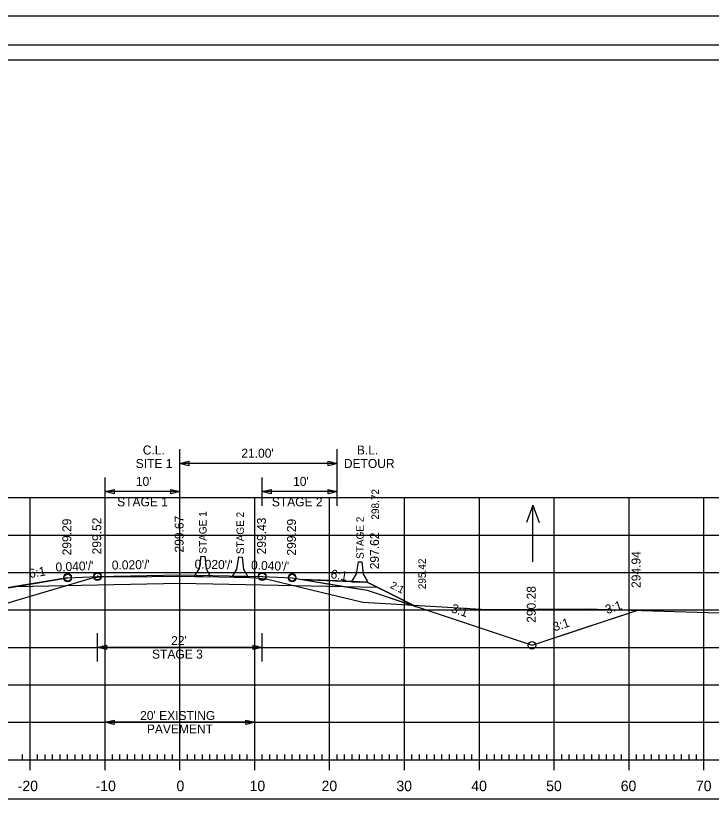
# Model space of a CAD drawing. Extents: x 1368713 to 1370673, y 380279 to 380950.
# Drawn here: x 1370130.4 to 1370223.2, y 380418.3 to 380523.8 of the extents above; entities that cross this region are included whole.
import ezdxf

# ---------------------------------------------------------------- set-up
doc = ezdxf.new("R2010")
doc.units = 0
for name, color, linetype in [('R_Alt Surface', 7, 'Continuous'), ('R_Axis', 7, 'Continuous'), ('R_Axis Annot', 7, 'Continuous'), ('R_Border', 7, 'Continuous'), ('R_CONC BARRIER', 7, 'Continuous'), ('R_Exist Surface', 7, 'Continuous'), ('R_Fin Surface', 7, 'Continuous'), ('R_Grid', 7, 'Continuous'), ('R_No Plot', 7, 'Continuous'), ('R_ROW Annot', 7, 'Continuous'), ('R_Stage 3 EW', 7, 'Continuous'), ('R_Water Annot', 7, 'Continuous'), ('R_Xsect Elev', 7, 'Continuous'), ('R_Xsect Slope', 7, 'Continuous')]:
    doc.layers.add(name, color=color, linetype=linetype)

msp = doc.modelspace()

# ---------------------------------------------------------------- linework, layer by layer
for points in [[(1370141.28, 380449.01), (1370141.28, 380448.94), (1370141.28, 380448.87), (1370141.28, 380448.85), (1370141.28, 380448.84)], [(1370163.28, 380448.94), (1370163.28, 380448.87), (1370163.28, 380448.85), (1370163.28, 380448.84)]]:
    msp.add_lwpolyline(points)
at = {"layer": 'R_Alt Surface'}
for points in [[(1370137.28, 380448.71), (1370127.28, 380447.04)], [(1370130.44, 380447.57), (1370141.28, 380447.78), (1370152.28, 380448), (1370163.28, 380447.78), (1370174.12, 380447.57)], [(1370167.28, 380448.71), (1370177.28, 380447.04)], [(1370177.28, 380448.14), (1370183.88, 380444.84)], [(1370174.12, 380447.57), (1370178.61, 380447.48)], [(1370177.28, 380447.04), (1370199.31, 380439.7)], [(1370199.31, 380439.7), (1370199.31, 380439.7), (1370213.3, 380444.36)]]:
    msp.add_lwpolyline(points, dxfattribs=at)
at = {"layer": 'R_Axis'}
for p, q in [((1370132.28, 380423.02), (1370132.28, 380425.82)), ((1370142.28, 380423.02), (1370142.28, 380425.82)), ((1370152.28, 380423.02), (1370152.28, 380425.82)), ((1370162.28, 380423.02), (1370162.28, 380425.82)), ((1370172.28, 380423.02), (1370172.28, 380425.82)), ((1370182.28, 380423.02), (1370182.28, 380425.82)), ((1370192.28, 380423.02), (1370192.28, 380425.82)), ((1370202.28, 380423.02), (1370202.28, 380425.82)), ((1370212.28, 380423.02), (1370212.28, 380425.82)), ((1370222.28, 380423.02), (1370222.28, 380425.82)), ((1370131.28, 380424.42), (1370131.28, 380425.12)), ((1370133.28, 380424.42), (1370133.28, 380425.12)), ((1370134.28, 380424.42), (1370134.28, 380425.12)), ((1370135.28, 380424.42), (1370135.28, 380425.12)), ((1370136.28, 380424.42), (1370136.28, 380425.12)), ((1370137.28, 380424.42), (1370137.28, 380425.12)), ((1370138.28, 380424.42), (1370138.28, 380425.12)), ((1370139.28, 380424.42), (1370139.28, 380425.12)), ((1370140.28, 380424.42), (1370140.28, 380425.12)), ((1370141.28, 380424.42), (1370141.28, 380425.12)), ((1370143.28, 380424.42), (1370143.28, 380425.12)), ((1370144.28, 380424.42), (1370144.28, 380425.12)), ((1370145.28, 380424.42), (1370145.28, 380425.12)), ((1370146.28, 380424.42), (1370146.28, 380425.12)), ((1370147.28, 380424.42), (1370147.28, 380425.12)), ((1370148.28, 380424.42), (1370148.28, 380425.12)), ((1370149.28, 380424.42), (1370149.28, 380425.12)), ((1370150.28, 380424.42), (1370150.28, 380425.12)), ((1370151.28, 380424.42), (1370151.28, 380425.12)), ((1370153.28, 380424.42), (1370153.28, 380425.12)), ((1370154.28, 380424.42), (1370154.28, 380425.12)), ((1370155.28, 380424.42), (1370155.28, 380425.12)), ((1370156.28, 380424.42), (1370156.28, 380425.12)), ((1370157.28, 380424.42), (1370157.28, 380425.12)), ((1370158.28, 380424.42), (1370158.28, 380425.12)), ((1370159.28, 380424.42), (1370159.28, 380425.12)), ((1370160.28, 380424.42), (1370160.28, 380425.12)), ((1370161.28, 380424.42), (1370161.28, 380425.12)), ((1370163.28, 380424.42), (1370163.28, 380425.12)), ((1370164.28, 380424.42), (1370164.28, 380425.12)), ((1370165.28, 380424.42), (1370165.28, 380425.12)), ((1370166.28, 380424.42), (1370166.28, 380425.12)), ((1370167.28, 380424.42), (1370167.28, 380425.12)), ((1370168.28, 380424.42), (1370168.28, 380425.12)), ((1370169.28, 380424.42), (1370169.28, 380425.12)), ((1370170.28, 380424.42), (1370170.28, 380425.12)), ((1370171.28, 380424.42), (1370171.28, 380425.12)), ((1370173.28, 380424.42), (1370173.28, 380425.12)), ((1370174.28, 380424.42), (1370174.28, 380425.12)), ((1370175.28, 380424.42), (1370175.28, 380425.12)), ((1370176.28, 380424.42), (1370176.28, 380425.12)), ((1370177.28, 380424.42), (1370177.28, 380425.12)), ((1370178.28, 380424.42), (1370178.28, 380425.12)), ((1370179.28, 380424.42), (1370179.28, 380425.12)), ((1370180.28, 380424.42), (1370180.28, 380425.12)), ((1370181.28, 380424.42), (1370181.28, 380425.12)), ((1370183.28, 380424.42), (1370183.28, 380425.12)), ((1370184.28, 380424.42), (1370184.28, 380425.12)), ((1370185.28, 380424.42), (1370185.28, 380425.12)), ((1370186.28, 380424.42), (1370186.28, 380425.12)), ((1370187.28, 380424.42), (1370187.28, 380425.12)), ((1370188.28, 380424.42), (1370188.28, 380425.12)), ((1370189.28, 380424.42), (1370189.28, 380425.12)), ((1370190.28, 380424.42), (1370190.28, 380425.12)), ((1370191.28, 380424.42), (1370191.28, 380425.12)), ((1370193.28, 380424.42), (1370193.28, 380425.12)), ((1370194.28, 380424.42), (1370194.28, 380425.12)), ((1370195.28, 380424.42), (1370195.28, 380425.12)), ((1370196.28, 380424.42), (1370196.28, 380425.12)), ((1370197.28, 380424.42), (1370197.28, 380425.12)), ((1370198.28, 380424.42), (1370198.28, 380425.12)), ((1370199.28, 380424.42), (1370199.28, 380425.12)), ((1370200.28, 380424.42), (1370200.28, 380425.12)), ((1370201.28, 380424.42), (1370201.28, 380425.12)), ((1370203.28, 380424.42), (1370203.28, 380425.12)), ((1370204.28, 380424.42), (1370204.28, 380425.12)), ((1370205.28, 380424.42), (1370205.28, 380425.12)), ((1370206.28, 380424.42), (1370206.28, 380425.12)), ((1370207.28, 380424.42), (1370207.28, 380425.12)), ((1370208.28, 380424.42), (1370208.28, 380425.12)), ((1370209.28, 380424.42), (1370209.28, 380425.12)), ((1370210.28, 380424.42), (1370210.28, 380425.12)), ((1370211.28, 380424.42), (1370211.28, 380425.12)), ((1370213.28, 380424.42), (1370213.28, 380425.12)), ((1370214.28, 380424.42), (1370214.28, 380425.12)), ((1370215.28, 380424.42), (1370215.28, 380425.12)), ((1370216.28, 380424.42), (1370216.28, 380425.12)), ((1370217.28, 380424.42), (1370217.28, 380425.12)), ((1370218.28, 380424.42), (1370218.28, 380425.12)), ((1370219.28, 380424.42), (1370219.28, 380425.12)), ((1370220.28, 380424.42), (1370220.28, 380425.12)), ((1370221.28, 380424.42), (1370221.28, 380425.12)), ((1370012.28, 380424.42), (1370292.28, 380424.42))]:
    msp.add_line(p, q, dxfattribs=at)
at = {"layer": 'R_Border'}
for p, q in [((1369994.28, 380519.88), (1370310.46, 380519.88)), ((1370146.8, 380519.62), (1370146.8, 380519.62)), ((1370146.8, 380519.62), (1370146.8, 380519.62))]:
    msp.add_line(p, q, dxfattribs=at)
at = {"layer": 'R_CONC BARRIER'}
for p, q in [((1370155.09, 380451.58), (1370155.59, 380451.57)), ((1370160.09, 380451.5), (1370160.59, 380451.49)), ((1370176.09, 380450.86), (1370176.59, 380450.85)), ((1370154.28, 380448.89), (1370154.29, 380449.06)), ((1370154.28, 380448.89), (1370156.28, 380448.85)), ((1370156.28, 380448.85), (1370156.29, 380449.02)), ((1370159.28, 380448.82), (1370159.29, 380448.99)), ((1370159.28, 380448.82), (1370161.28, 380448.78)), ((1370161.28, 380448.78), (1370161.29, 380448.95)), ((1370175.28, 380448.18), (1370175.29, 380448.35)), ((1370175.28, 380448.18), (1370177.28, 380448.14)), ((1370177.28, 380448.14), (1370177.29, 380448.31))]:
    msp.add_line(p, q, dxfattribs=at)
for points in [[(1370155.09, 380451.58), (1370154.84, 380449.94), (1370154.29, 380449.06)], [(1370155.59, 380451.57), (1370155.77, 380449.92), (1370156.29, 380449.02)], [(1370160.09, 380451.5), (1370159.84, 380449.87), (1370159.29, 380448.99)], [(1370160.59, 380451.49), (1370160.77, 380449.85), (1370161.29, 380448.95)], [(1370176.09, 380450.86), (1370175.84, 380449.23), (1370175.29, 380448.35)], [(1370176.59, 380450.85), (1370176.77, 380449.21), (1370177.29, 380448.31)]]:
    msp.add_lwpolyline(points, dxfattribs=at)
at = {"layer": 'R_Exist Surface'}
msp.add_lwpolyline([(1370127.85, 380444.92), (1370130.37, 380445.68), (1370140.63, 380448.69), (1370141.3, 380448.78), (1370141.85, 380448.86), (1370148.53, 380448.9), (1370151.93, 380448.92), (1370155.37, 380448.88), (1370161.6, 380448.77), (1370162.51, 380448.71), (1370163.96, 380448.53), (1370169.84, 380447.12), (1370176.72, 380445.46), (1370193.29, 380444.5), (1370206.6, 380444.55), (1370231.71, 380443.82), (1370238.87, 380443.76), (1370241.47, 380442.81), (1370252.47, 380438.45), (1370256.7, 380438.5), (1370261.72, 380438.46), (1370272.45, 380441.8), (1370280.64, 380444.29), (1370292.28, 380444.39)], dxfattribs=at)
at = {"layer": 'R_Fin Surface'}
for points in [[(1370086.4, 380444.54), (1370095.2, 380441.62), (1370103.09, 380438.98), (1370127.28, 380447.04), (1370130.44, 380447.57), (1370137.28, 380448.71), (1370141.28, 380448.87), (1370152.28, 380449.09), (1370163.28, 380448.87), (1370167.28, 380448.71), (1370174.12, 380447.57), (1370177.28, 380447.04), (1370199.31, 380439.7), (1370205.6, 380441.81), (1370213.3, 380444.36)], [(1370137.28, 380448.71), (1370141.28, 380448.87), (1370152.28, 380449.09), (1370163.28, 380448.87), (1370167.28, 380448.71)], [(1370168.6, 380448.49), (1370177.28, 380448.14)]]:
    msp.add_lwpolyline(points, dxfattribs=at)
at = {"layer": 'R_Grid'}
for p, q in [((1370012.28, 380459.42), (1370292.28, 380459.42)), ((1370132.28, 380424.42), (1370132.28, 380459.42)), ((1370142.28, 380424.42), (1370142.28, 380459.42)), ((1370152.28, 380424.42), (1370152.28, 380459.42)), ((1370162.28, 380424.42), (1370162.28, 380459.42)), ((1370172.28, 380424.42), (1370172.28, 380459.42)), ((1370182.28, 380424.42), (1370182.28, 380459.42)), ((1370192.28, 380424.42), (1370192.28, 380459.42)), ((1370202.28, 380424.42), (1370202.28, 380459.42)), ((1370212.28, 380424.42), (1370212.28, 380459.42)), ((1370222.28, 380424.42), (1370222.28, 380459.42)), ((1370012.28, 380454.42), (1370292.28, 380454.42)), ((1370012.28, 380449.42), (1370292.28, 380449.42)), ((1370012.28, 380444.42), (1370292.28, 380444.42)), ((1370012.28, 380439.42), (1370292.28, 380439.42)), ((1370012.28, 380434.42), (1370292.28, 380434.42)), ((1370012.28, 380429.42), (1370292.28, 380429.42)), ((1370012.28, 380424.42), (1370292.28, 380424.42))]:
    msp.add_line(p, q, dxfattribs=at)
at = {"layer": 'R_No Plot'}
for points in [[(1369981.88, 380523.77), (1370315.22, 380523.77), (1370315.22, 380310.43), (1369981.88, 380310.43)], [(1370308.46, 380419.15), (1369996.28, 380419.15), (1369996.28, 380517.88), (1370245.82, 380517.88), (1370245.82, 380508), (1370263.36, 380508), (1370287.46, 380508), (1370287.46, 380485.66), (1370308.46, 380485.66)], [(1369996.28, 380517.88), (1370245.82, 380517.88), (1370245.82, 380508), (1370263.36, 380508), (1370287.46, 380508), (1370287.46, 380485.66), (1370308.46, 380485.66), (1370308.46, 380316.42), (1369996.28, 380316.42)]]:
    msp.add_lwpolyline(points, close=True, dxfattribs=at)
for centre in [(1370137.28, 380448.78), (1370137.28, 380448.71), (1370137.28, 380448.71), (1370137.28, 380448.69), (1370137.28, 380448.68), (1370141.28, 380448.94), (1370141.28, 380448.87), (1370141.28, 380448.87), (1370141.28, 380448.85), (1370141.28, 380448.84), (1370163.28, 380448.94), (1370163.28, 380448.87), (1370163.28, 380448.87), (1370163.28, 380448.85), (1370163.28, 380448.84), (1370167.28, 380448.78), (1370167.28, 380448.71), (1370167.28, 380448.71), (1370167.28, 380448.69), (1370167.28, 380448.68), (1370199.31, 380439.7)]:
    msp.add_circle(centre, 0.5, dxfattribs=at)
at = {"layer": 'R_ROW Annot'}
for p, q in [((1370152.28, 380462.1), (1370152.28, 380465.87)), ((1370173.28, 380462.1), (1370173.28, 380465.87)), ((1370173.28, 380463.98), (1370152.28, 380463.98)), ((1370142.28, 380458.33), (1370142.28, 380462.1)), ((1370152.28, 380458.33), (1370152.28, 380462.1)), ((1370163.28, 380458.33), (1370163.28, 380462.1)), ((1370173.28, 380458.33), (1370173.28, 380462.1)), ((1370152.28, 380460.22), (1370142.28, 380460.22)), ((1370173.28, 380460.22), (1370163.28, 380460.22)), ((1370141.28, 380437.53), (1370141.28, 380441.3)), ((1370163.28, 380437.53), (1370163.28, 380441.3)), ((1370163.28, 380439.42), (1370141.28, 380439.42)), ((1370142.28, 380427.53), (1370142.28, 380431.3)), ((1370162.28, 380427.53), (1370162.28, 380431.3)), ((1370162.28, 380429.42), (1370142.28, 380429.42))]:
    msp.add_line(p, q, dxfattribs=at)
for points in [[(1370153.48, 380463.68), (1370152.28, 380463.98), (1370153.48, 380464.28)], [(1370172.08, 380464.28), (1370173.28, 380463.98), (1370172.08, 380463.68)], [(1370143.48, 380459.92), (1370142.28, 380460.22), (1370143.48, 380460.52)], [(1370151.08, 380460.52), (1370152.28, 380460.22), (1370151.08, 380459.92)], [(1370164.48, 380459.92), (1370163.28, 380460.22), (1370164.48, 380460.52)], [(1370172.08, 380460.52), (1370173.28, 380460.22), (1370172.08, 380459.92)], [(1370142.48, 380439.12), (1370141.28, 380439.42), (1370142.48, 380439.72)], [(1370162.08, 380439.72), (1370163.28, 380439.42), (1370162.08, 380439.12)], [(1370143.48, 380429.12), (1370142.28, 380429.42), (1370143.48, 380429.72)], [(1370161.08, 380429.72), (1370162.28, 380429.42), (1370161.08, 380429.12)]]:
    msp.add_lwpolyline(points, close=True, dxfattribs=at)
at = {"layer": 'R_Stage 3 EW'}
for p, q in [((1370174.12, 380447.57), (1370177.28, 380447.04)), ((1370177.28, 380447.04), (1370183.14, 380445.09)), ((1370183.14, 380445.09), (1370183.88, 380444.84))]:
    msp.add_line(p, q, dxfattribs=at)
for points in [[(1370168.6, 380448.49), (1370172.28, 380447.87), (1370174.12, 380447.57)], [(1370177.28, 380448.14), (1370175.28, 380448.22), (1370172.28, 380448.34), (1370168.6, 380448.49)], [(1370183.88, 380444.84), (1370183.42, 380445.07), (1370178.61, 380447.48), (1370177.28, 380448.14)]]:
    msp.add_lwpolyline(points, dxfattribs=at)
at = {"layer": 'R_Water Annot'}
for p, q in [((1370199.41, 380458.4), (1370198.57, 380456.09)), ((1370199.41, 380450.86), (1370199.41, 380458.4)), ((1370199.41, 380458.4), (1370200.25, 380456.09))]:
    msp.add_line(p, q, dxfattribs=at)

# ---------------------------------------------------------------- texts
at = {"layer": 'R_Axis Annot'}
for s, p in [('-20', (1370130.62, 380420.22)), ('-10', (1370141.02, 380420.22)), ('0', (1370151.83, 380420.22)), ('10', (1370161.59, 380420.22)), ('20', (1370171.2, 380420.22)), ('30', (1370181.2, 380420.22)), ('40', (1370191.2, 380420.22)), ('50', (1370201.2, 380420.22)), ('60', (1370211.16, 380420.22)), ('70', (1370221.2, 380420.22))]:
    msp.add_text(s, height=1.4, dxfattribs=at).set_placement(p)
at = {"layer": 'R_CONC BARRIER'}
for s, p in [(' STAGE 1', (1370155.84, 380451.57)), (' STAGE 2', (1370160.84, 380451.5)), (' STAGE 2', (1370176.84, 380450.86))]:
    msp.add_text(s, height=1, rotation=90, dxfattribs=at).set_placement(p)
at = {"layer": 'R_ROW Annot'}
for s, p in [('C.L.', (1370147.32, 380465.18)), ("21.00'", (1370160.49, 380464.75)), ('B.L.', (1370175.92, 380465.18)), ('SITE 1', (1370146.38, 380463.38)), ('DETOUR', (1370174.18, 380463.38)), ("10'", (1370146.4, 380460.99)), ("10'", (1370167.4, 380460.99)), ('STAGE 1', (1370143.9, 380458.25)), ('STAGE 2', (1370164.56, 380458.25)), ("22'", (1370151.11, 380439.72)), ('STAGE 3', (1370148.56, 380437.92)), ("20' EXISTING", (1370146.97, 380429.72)), ('PAVEMENT', (1370147.87, 380427.92))]:
    msp.add_text(s, height=1.2, dxfattribs=at).set_placement(p)
at = {"layer": 'R_Xsect Elev'}
for s, height, p in [('298.72', 1, (1370178.87, 380456.48)), ('299.29', 1.2, (1370137.78, 380451.71)), ('299.52', 1.2, (1370141.78, 380451.84)), ('299.67', 1.2, (1370152.78, 380452.09)), ('299.43', 1.2, (1370163.78, 380451.84)), ('299.29', 1.2, (1370167.78, 380451.68)), ('297.62', 1.2, (1370178.87, 380449.85)), ('294.94', 1.2, (1370213.8, 380447.36)), ('295.42', 1, (1370185.13, 380447.19)), ('290.28', 1.2, (1370199.81, 380442.7))]:
    msp.add_text(s, height=height, rotation=90, dxfattribs=at).set_placement(p)
at = {"layer": 'R_Xsect Slope'}
for s, height, rotation, p in [("0.040'/'", 1.2, 2.2906, (1370135.69, 380449.54)), ("0.020'/'", 1.2, 1.1458, (1370143.2, 380449.8)), ("0.020'/'", 1.2, 358.8542, (1370154.24, 380449.95)), ("0.040'/'", 1.2, 357.7094, (1370161.76, 380449.83)), ('6:1', 1.2, 9.4623, (1370132.22, 380448.67)), ('6:1', 1.2, 350.5377, (1370172.35, 380448.67)), ('2:1', 1, 333.4349, (1370180.29, 380447.4)), ('3:1', 1.2, 18.3163, (1370209.32, 380443.86)), ('3:1', 1.2, 341.5651, (1370188.42, 380444.15)), ('3:1', 1.2, 18.58, (1370202.33, 380441.53))]:
    msp.add_text(s, height=height, rotation=rotation, dxfattribs=at).set_placement(p)

doc.saveas('drawing.dxf')
